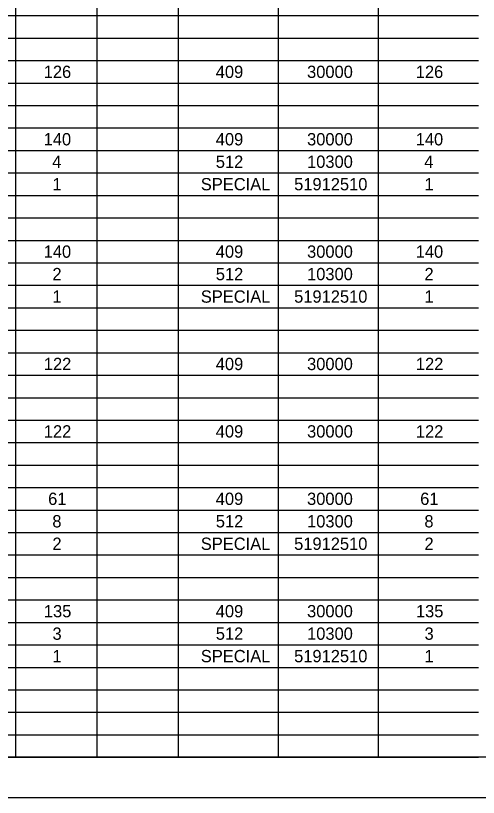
# Model space of a CAD drawing. Extents: x 0 to 34, y 0 to 22.
# Drawn here: x 9.6 to 15.36, y 0 to 9.74 of the extents above; entities that cross this region are included whole.
import ezdxf

# ---------------------------------------------------------------- set-up
doc = ezdxf.new("R2010")
doc.units = 0
for name, color, linetype in [('SH_Border', 7, 'Continuous'), ('SH_Cut_Line', 7, 'Continuous'), ('SH_Text', 7, 'Continuous')]:
    doc.layers.add(name, color=color, linetype=linetype)

msp = doc.modelspace()

# ---------------------------------------------------------------- linework, layer by layer
at = {"layer": 'SH_Border'}
msp.add_lwpolyline([(1.5, 21.5), (33.5, 21.5), (33.5, 0.5), (1.5, 0.5)], close=True, dxfattribs=at)
at = {"layer": 'SH_Cut_Line'}
msp.add_lwpolyline([(0, 0), (34, 0), (34, 22), (0, 22)], close=True, dxfattribs=at)
at = {"layer": 'SH_Text'}
for p, q in [((9.5987, 10.02), (9.5987, 9.74)), ((10.6111, 10.02), (10.6111, 9.74)), ((11.6234, 10.02), (11.6234, 9.74)), ((12.8694, 10.02), (12.8694, 9.74)), ((14.1153, 10.02), (14.1153, 9.74)), ((8.5864, 9.74), (9.5987, 9.74)), ((9.5987, 9.74), (11.6234, 9.74)), ((9.5987, 9.74), (9.5987, 8.9)), ((10.6111, 9.74), (10.6111, 8.9)), ((11.6234, 9.74), (12.8694, 9.74)), ((11.6234, 9.74), (11.6234, 8.9)), ((12.8694, 9.74), (14.1153, 9.74)), ((12.8694, 9.74), (12.8694, 8.9)), ((14.1153, 9.74), (15.3613, 9.74)), ((14.1153, 9.74), (14.1153, 8.9)), ((8.5864, 9.46), (9.5987, 9.46)), ((9.5987, 9.46), (11.6234, 9.46)), ((11.6234, 9.46), (12.8694, 9.46)), ((12.8694, 9.46), (14.1153, 9.46)), ((14.1153, 9.46), (15.3613, 9.46)), ((8.5864, 9.18), (9.5987, 9.18)), ((9.5987, 9.18), (11.6234, 9.18)), ((11.6234, 9.18), (12.8694, 9.18)), ((12.8694, 9.18), (14.1153, 9.18)), ((14.1153, 9.18), (15.3613, 9.18)), ((8.5864, 8.9), (9.5987, 8.9)), ((9.5987, 8.9), (11.6234, 8.9)), ((9.5987, 8.9), (9.5987, 8.34)), ((10.6111, 8.9), (10.6111, 8.34)), ((11.6234, 8.9), (12.8694, 8.9)), ((11.6234, 8.9), (11.6234, 8.34)), ((12.8694, 8.9), (14.1153, 8.9)), ((12.8694, 8.9), (12.8694, 8.34)), ((14.1153, 8.9), (15.3613, 8.9)), ((14.1153, 8.9), (14.1153, 8.34)), ((8.5864, 8.62), (9.5987, 8.62)), ((9.5987, 8.62), (11.6234, 8.62)), ((11.6234, 8.62), (12.8694, 8.62)), ((12.8694, 8.62), (14.1153, 8.62)), ((14.1153, 8.62), (15.3613, 8.62)), ((8.5864, 8.34), (9.5987, 8.34)), ((9.5987, 8.34), (11.6234, 8.34)), ((9.5987, 8.34), (9.5987, 7.5)), ((10.6111, 8.34), (10.6111, 7.5)), ((11.6234, 8.34), (12.8694, 8.34)), ((11.6234, 8.34), (11.6234, 7.5)), ((12.8694, 8.34), (14.1153, 8.34)), ((12.8694, 8.34), (12.8694, 7.5)), ((14.1153, 8.34), (15.3613, 8.34)), ((14.1153, 8.34), (14.1153, 7.5)), ((8.5864, 8.06), (9.5987, 8.06)), ((9.5987, 8.06), (11.6234, 8.06)), ((11.6234, 8.06), (12.8694, 8.06)), ((12.8694, 8.06), (14.1153, 8.06)), ((14.1153, 8.06), (15.3613, 8.06)), ((8.5864, 7.78), (9.5987, 7.78)), ((9.5987, 7.78), (11.6234, 7.78)), ((11.6234, 7.78), (12.8694, 7.78)), ((12.8694, 7.78), (14.1153, 7.78)), ((14.1153, 7.78), (15.3613, 7.78)), ((8.5864, 7.5), (9.5987, 7.5)), ((9.5987, 7.5), (11.6234, 7.5)), ((9.5987, 7.5), (9.5987, 6.94)), ((10.6111, 7.5), (10.6111, 6.94)), ((11.6234, 7.5), (12.8694, 7.5)), ((11.6234, 7.5), (11.6234, 6.94)), ((12.8694, 7.5), (14.1153, 7.5)), ((12.8694, 7.5), (12.8694, 6.94)), ((14.1153, 7.5), (15.3613, 7.5)), ((14.1153, 7.5), (14.1153, 6.94)), ((8.5864, 7.22), (9.5987, 7.22)), ((9.5987, 7.22), (11.6234, 7.22)), ((11.6234, 7.22), (12.8694, 7.22)), ((12.8694, 7.22), (14.1153, 7.22)), ((14.1153, 7.22), (15.3613, 7.22)), ((8.5864, 6.94), (9.5987, 6.94)), ((9.5987, 6.94), (11.6234, 6.94)), ((9.5987, 6.94), (9.5987, 6.1)), ((10.6111, 6.94), (10.6111, 6.1)), ((11.6234, 6.94), (12.8694, 6.94)), ((11.6234, 6.94), (11.6234, 6.1)), ((12.8694, 6.94), (14.1153, 6.94)), ((12.8694, 6.94), (12.8694, 6.1)), ((14.1153, 6.94), (15.3613, 6.94)), ((14.1153, 6.94), (14.1153, 6.1)), ((8.5864, 6.66), (9.5987, 6.66)), ((9.5987, 6.66), (11.6234, 6.66)), ((11.6234, 6.66), (12.8694, 6.66)), ((12.8694, 6.66), (14.1153, 6.66)), ((14.1153, 6.66), (15.3613, 6.66)), ((8.5864, 6.38), (9.5987, 6.38)), ((9.5987, 6.38), (11.6234, 6.38)), ((11.6234, 6.38), (12.8694, 6.38)), ((12.8694, 6.38), (14.1153, 6.38)), ((14.1153, 6.38), (15.3613, 6.38)), ((8.5864, 6.1), (9.5987, 6.1)), ((9.5987, 6.1), (11.6234, 6.1)), ((9.5987, 6.1), (9.5987, 4.98)), ((10.6111, 6.1), (10.6111, 4.98)), ((11.6234, 6.1), (12.8694, 6.1)), ((11.6234, 6.1), (11.6234, 4.98)), ((12.8694, 6.1), (14.1153, 6.1)), ((12.8694, 6.1), (12.8694, 4.98)), ((14.1153, 6.1), (15.3613, 6.1)), ((14.1153, 6.1), (14.1153, 4.98)), ((8.5864, 5.82), (9.5987, 5.82)), ((9.5987, 5.82), (11.6234, 5.82)), ((11.6234, 5.82), (12.8694, 5.82)), ((12.8694, 5.82), (14.1153, 5.82)), ((14.1153, 5.82), (15.3613, 5.82)), ((8.5864, 5.54), (9.5987, 5.54)), ((9.5987, 5.54), (11.6234, 5.54)), ((11.6234, 5.54), (12.8694, 5.54)), ((12.8694, 5.54), (14.1153, 5.54)), ((14.1153, 5.54), (15.3613, 5.54)), ((8.5864, 5.26), (9.5987, 5.26)), ((9.5987, 5.26), (11.6234, 5.26)), ((11.6234, 5.26), (12.8694, 5.26)), ((12.8694, 5.26), (14.1153, 5.26)), ((14.1153, 5.26), (15.3613, 5.26)), ((8.5864, 4.98), (9.5987, 4.98)), ((9.5987, 4.98), (11.6234, 4.98)), ((9.5987, 4.98), (9.5987, 4.7)), ((10.6111, 4.98), (10.6111, 4.7)), ((11.6234, 4.98), (12.8694, 4.98)), ((11.6234, 4.98), (11.6234, 4.7)), ((12.8694, 4.98), (14.1153, 4.98)), ((12.8694, 4.98), (12.8694, 4.7)), ((14.1153, 4.98), (15.3613, 4.98)), ((14.1153, 4.98), (14.1153, 4.7)), ((8.5864, 4.7), (9.5987, 4.7)), ((9.5987, 4.7), (11.6234, 4.7)), ((9.5987, 4.7), (9.5987, 3.58)), ((10.6111, 4.7), (10.6111, 3.58)), ((11.6234, 4.7), (12.8694, 4.7)), ((11.6234, 4.7), (11.6234, 3.58)), ((12.8694, 4.7), (14.1153, 4.7)), ((12.8694, 4.7), (12.8694, 3.58)), ((14.1153, 4.7), (15.3613, 4.7)), ((14.1153, 4.7), (14.1153, 3.58)), ((8.5864, 4.42), (9.5987, 4.42)), ((9.5987, 4.42), (11.6234, 4.42)), ((11.6234, 4.42), (12.8694, 4.42)), ((12.8694, 4.42), (14.1153, 4.42)), ((14.1153, 4.42), (15.3613, 4.42)), ((8.5864, 4.14), (9.5987, 4.14)), ((9.5987, 4.14), (11.6234, 4.14)), ((11.6234, 4.14), (12.8694, 4.14)), ((12.8694, 4.14), (14.1153, 4.14)), ((14.1153, 4.14), (15.3613, 4.14)), ((8.5864, 3.86), (9.5987, 3.86)), ((9.5987, 3.86), (11.6234, 3.86)), ((11.6234, 3.86), (12.8694, 3.86)), ((12.8694, 3.86), (14.1153, 3.86)), ((14.1153, 3.86), (15.3613, 3.86)), ((8.5864, 3.58), (9.5987, 3.58)), ((9.5987, 3.58), (11.6234, 3.58)), ((9.5987, 3.58), (9.5987, 3.3)), ((10.6111, 3.58), (10.6111, 3.3)), ((11.6234, 3.58), (12.8694, 3.58)), ((11.6234, 3.58), (11.6234, 3.3)), ((12.8694, 3.58), (14.1153, 3.58)), ((12.8694, 3.58), (12.8694, 3.3)), ((14.1153, 3.58), (15.3613, 3.58)), ((14.1153, 3.58), (14.1153, 3.3)), ((8.5864, 3.3), (9.5987, 3.3)), ((9.5987, 3.3), (11.6234, 3.3)), ((9.5987, 3.3), (9.5987, 2.18)), ((10.6111, 3.3), (10.6111, 2.18)), ((11.6234, 3.3), (12.8694, 3.3)), ((11.6234, 3.3), (11.6234, 2.18)), ((12.8694, 3.3), (14.1153, 3.3)), ((12.8694, 3.3), (12.8694, 2.18)), ((14.1153, 3.3), (15.3613, 3.3)), ((14.1153, 3.3), (14.1153, 2.18)), ((8.5864, 3.02), (9.5987, 3.02)), ((9.5987, 3.02), (11.6234, 3.02)), ((11.6234, 3.02), (12.8694, 3.02)), ((12.8694, 3.02), (14.1153, 3.02)), ((14.1153, 3.02), (15.3613, 3.02)), ((8.5864, 2.74), (9.5987, 2.74)), ((9.5987, 2.74), (11.6234, 2.74)), ((11.6234, 2.74), (12.8694, 2.74)), ((12.8694, 2.74), (14.1153, 2.74)), ((14.1153, 2.74), (15.3613, 2.74)), ((8.5864, 2.46), (9.5987, 2.46)), ((9.5987, 2.46), (11.6234, 2.46)), ((11.6234, 2.46), (12.8694, 2.46)), ((12.8694, 2.46), (14.1153, 2.46)), ((14.1153, 2.46), (15.3613, 2.46)), ((8.5864, 2.18), (9.5987, 2.18)), ((9.5987, 2.18), (11.6234, 2.18)), ((9.5987, 2.18), (9.5987, 1.9)), ((10.6111, 2.18), (10.6111, 1.9)), ((11.6234, 2.18), (12.8694, 2.18)), ((11.6234, 2.18), (11.6234, 1.9)), ((12.8694, 2.18), (14.1153, 2.18)), ((12.8694, 2.18), (12.8694, 1.9)), ((14.1153, 2.18), (15.3613, 2.18)), ((14.1153, 2.18), (14.1153, 1.9)), ((8.5864, 1.9), (9.5987, 1.9)), ((9.5987, 1.9), (11.6234, 1.9)), ((9.5987, 1.9), (9.5987, 0.78)), ((10.6111, 1.9), (10.6111, 0.78)), ((11.6234, 1.9), (12.8694, 1.9)), ((11.6234, 1.9), (11.6234, 0.78)), ((12.8694, 1.9), (14.1153, 1.9)), ((12.8694, 1.9), (12.8694, 0.78)), ((14.1153, 1.9), (15.3613, 1.9)), ((14.1153, 1.9), (14.1153, 0.78)), ((8.5864, 1.62), (9.5987, 1.62)), ((9.5987, 1.62), (11.6234, 1.62)), ((11.6234, 1.62), (12.8694, 1.62)), ((12.8694, 1.62), (14.1153, 1.62)), ((14.1153, 1.62), (15.3613, 1.62)), ((8.5864, 1.34), (9.5987, 1.34)), ((9.5987, 1.34), (11.6234, 1.34)), ((11.6234, 1.34), (12.8694, 1.34)), ((12.8694, 1.34), (14.1153, 1.34)), ((14.1153, 1.34), (15.3613, 1.34)), ((8.5864, 1.06), (9.5987, 1.06)), ((9.5987, 1.06), (11.6234, 1.06)), ((11.6234, 1.06), (12.8694, 1.06)), ((12.8694, 1.06), (14.1153, 1.06)), ((14.1153, 1.06), (15.3613, 1.06)), ((8.5864, 0.78), (9.5987, 0.78)), ((9.5987, 0.78), (11.6234, 0.78)), ((9.5987, 0.78), (9.5987, 0.5)), ((10.6111, 0.78), (10.6111, 0.5)), ((11.6234, 0.78), (12.8694, 0.78)), ((11.6234, 0.78), (11.6234, 0.5)), ((12.8694, 0.78), (14.1153, 0.78)), ((12.8694, 0.78), (12.8694, 0.5)), ((14.1153, 0.78), (15.3613, 0.78)), ((14.1153, 0.78), (14.1153, 0.5)), ((8.5864, 0.5), (9.5987, 0.5)), ((9.5987, 0.5), (11.6234, 0.5)), ((11.6234, 0.5), (12.8694, 0.5)), ((12.8694, 0.5), (14.1153, 0.5)), ((14.1153, 0.5), (15.3613, 0.5))]:
    msp.add_line(p, q, dxfattribs=at)

# ---------------------------------------------------------------- texts
for s, height, p in [('126', 0.15333, (9.9482, 8.9633)), ('409', 0.15333, (12.0909, 8.9633)), ('30000', 0.15333, (13.228, 8.9633)), ('126', 0.15333, (14.5816, 8.9633)), ('140', 0.15333, (9.9477, 8.1233)), ('409', 0.15333, (12.0909, 8.1233)), ('30000', 0.15333, (13.228, 8.1233)), ('140', 0.15333, (14.5811, 8.1233)), ('4', 0.1533, (10.0543, 7.8433)), ('512', 0.15333, (12.0914, 7.8433)), ('10300', 0.15333, (13.228, 7.8433)), ('4', 0.1533, (14.6877, 7.8433)), ('1', 0.1533, (10.057, 7.5633)), ('SPECIAL', 0.15333, (11.9048, 7.5633)), ('51912510', 0.15333, (13.0672, 7.5633)), ('1', 0.1533, (14.6904, 7.5633)), ('140', 0.15333, (9.9477, 6.7233)), ('409', 0.15333, (12.0909, 6.7233)), ('30000', 0.15333, (13.228, 6.7233)), ('140', 0.15333, (14.5811, 6.7233)), ('2', 0.1533, (10.0572, 6.4433)), ('512', 0.15333, (12.0914, 6.4433)), ('10300', 0.15333, (13.228, 6.4433)), ('2', 0.1533, (14.6906, 6.4433)), ('1', 0.1533, (10.057, 6.1633)), ('SPECIAL', 0.15333, (11.9048, 6.1633)), ('51912510', 0.15333, (13.0672, 6.1633)), ('1', 0.1533, (14.6904, 6.1633)), ('122', 0.15333, (9.9499, 5.3233)), ('409', 0.15333, (12.0909, 5.3233)), ('30000', 0.15333, (13.228, 5.3233)), ('122', 0.15333, (14.5833, 5.3233)), ('122', 0.15333, (9.9499, 4.4833)), ('409', 0.15333, (12.0909, 4.4833)), ('30000', 0.15333, (13.228, 4.4833)), ('122', 0.15333, (14.5833, 4.4833)), ('61', 0.15333, (10.0034, 3.6433)), ('409', 0.15333, (12.0909, 3.6433)), ('30000', 0.15333, (13.228, 3.6433)), ('61', 0.15333, (14.6368, 3.6433)), ('8', 0.1533, (10.0556, 3.3633)), ('512', 0.15333, (12.0914, 3.3633)), ('10300', 0.15333, (13.228, 3.3633)), ('8', 0.1533, (14.689, 3.3633)), ('2', 0.1533, (10.0572, 3.0833)), ('SPECIAL', 0.15333, (11.9048, 3.0833)), ('51912510', 0.15333, (13.0672, 3.0833)), ('2', 0.1533, (14.6906, 3.0833)), ('135', 0.15333, (9.9503, 2.2433)), ('409', 0.15333, (12.0909, 2.2433)), ('30000', 0.15333, (13.228, 2.2433)), ('135', 0.15333, (14.5837, 2.2433)), ('3', 0.1533, (10.0577, 1.9633)), ('512', 0.15333, (12.0914, 1.9633)), ('10300', 0.15333, (13.228, 1.9633)), ('3', 0.1533, (14.6911, 1.9633)), ('1', 0.1533, (10.057, 1.6833)), ('SPECIAL', 0.15333, (11.9048, 1.6833)), ('51912510', 0.15333, (13.0672, 1.6833)), ('1', 0.1533, (14.6904, 1.6833))]:
    msp.add_text(s, height=height, dxfattribs=at).set_placement(p)

doc.saveas('drawing.dxf')
